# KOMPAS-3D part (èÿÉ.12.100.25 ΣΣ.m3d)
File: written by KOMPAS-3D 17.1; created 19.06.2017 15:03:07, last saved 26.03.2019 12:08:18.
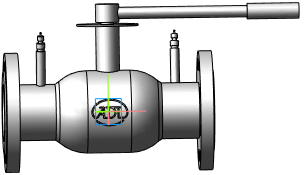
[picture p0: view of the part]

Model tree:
1. Операция без истории:2  (labels: Сталь 20  ГОСТ 1050-88)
